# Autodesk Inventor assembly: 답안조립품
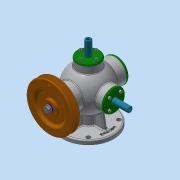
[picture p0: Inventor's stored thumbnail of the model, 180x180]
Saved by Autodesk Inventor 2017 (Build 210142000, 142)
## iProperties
Part Number: 답안조립품
Material: 일반
Document SubType Name: Assembly
Designer: MRC
Mass: 3778.23 g
Surface Area: 2410.88 cm^2
Volume: 904.616 cm^3
Density: 4.17662 g/cm^3
Author: MRC
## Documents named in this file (17)
- C:\Users\MRC\Desktop\600911V1003\답안조립품.iam
- C:\Users\MRC\Desktop\600911V1003\본체.ipt
- C:\Users\MRC\Desktop\600911V1003\V-벨트풀리.ipt
- C:\Users\MRC\Desktop\600911V1003\너트 M8x1.ipt
- C:\Users\MRC\Desktop\600911V1003\뒤커버.ipt
- C:\Users\MRC\Desktop\600911V1003\베어링 6202.ipt
- C:\Users\MRC\Desktop\600911V1003\본체커버.ipt
- C:\Users\MRC\Desktop\600911V1003\볼트 M4.ipt
- C:\Users\MRC\Desktop\600911V1003\스프링1.ipt
- C:\Users\MRC\Desktop\600911V1003\스프링2.ipt
- C:\Users\MRC\Desktop\600911V1003\슬라이드 커버.ipt
- C:\Users\MRC\Desktop\600911V1003\슬라이드.ipt
- C:\Users\MRC\Desktop\600911V1003\앞커버.ipt
- C:\Users\MRC\Desktop\600911V1003\오일 실.ipt
- C:\Users\MRC\Desktop\600911V1003\와셔 8x17.ipt
- C:\Users\MRC\Desktop\600911V1003\축.ipt
- C:\Users\MRC\Desktop\600911V1003\키 4x4.ipt
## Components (1 placed, 1 different names)
1. V-벨트풀리:1
